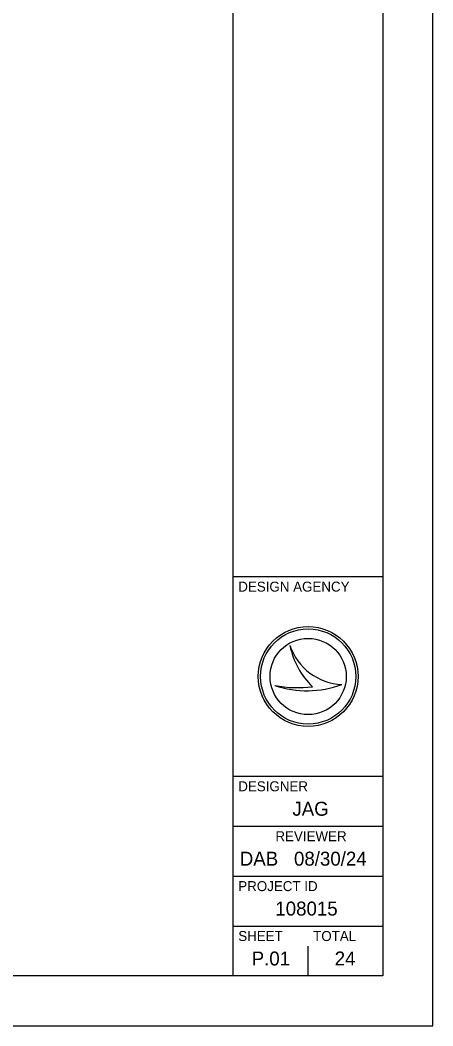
# Model space of a CAD drawing. Extents: x -10.1 to 68, y -9.5 to 29.2.
# Drawn here: x 29.86 to 34, y 0 to 10.07 of the extents above; entities that cross this region are included whole.
import ezdxf

# ---------------------------------------------------------------- set-up
doc = ezdxf.new("R2010")
doc.units = 0
for name, color, linetype in [('SH_Border', 7, 'Continuous'), ('SH_Cut_Line', 7, 'Continuous'), ('SH_Data', 7, 'Continuous')]:
    doc.layers.add(name, color=color, linetype=linetype)

msp = doc.modelspace()

# ---------------------------------------------------------------- linework, layer by layer
at = {"layer": 'SH_Border'}
for p, q in [((32, 0.5), (32, 21.5)), ((32, 4.5), (33.5, 4.5)), ((32, 2.5), (33.5, 2.5)), ((32, 2), (33.5, 2)), ((32, 1.5), (33.5, 1.5)), ((32, 1), (33.5, 1))]:
    msp.add_line(p, q, dxfattribs=at)
msp.add_lwpolyline([(1.5, 21.5), (33.5, 21.5), (33.5, 0.5), (1.5, 0.5)], close=True, dxfattribs=at)
at = {"layer": 'SH_Cut_Line'}
msp.add_lwpolyline([(0, 0), (34, 0), (34, 22), (0, 22)], close=True, dxfattribs=at)
at = {"layer": 'SH_Data'}
for p, q in [((32.567, 3.81), (32.567, 3.81)), ((32.75, 3.5), (32.75, 3.5)), ((32.417, 3.41), (32.417, 3.41)), ((33.087, 3.419), (33.087, 3.419)), ((32.75, 0.5), (32.75, 0.8)), ((32.375, 0.675), (32.375, 0.675))]:
    msp.add_line(p, q, dxfattribs=at)
for radius in [0.5, 0.477, 0.477, 0.382]:
    msp.add_circle((32.75, 3.5), radius, dxfattribs=at)
for centre, radius, start, end in [((33.116, 3.998), 0.58, 198.9257, 198.9319), ((33.347, 3.97), 0.796, 191.6379, 191.6421), ((33.116, 3.998), 0.58, 198.9319, 267.1657), ((33.347, 3.97), 0.796, 191.6421, 226.0947), ((32.739, 4.37), 1.013, 251.4576, 290.0832), ((32.648, 4.654), 1.266, 259.4964, 259.4995), ((32.739, 4.37), 1.013, 251.4527, 251.4576), ((32.648, 4.654), 1.266, 259.4995, 276.6672)]:
    msp.add_arc(centre, radius, start, end, dxfattribs=at)

# ---------------------------------------------------------------- texts
for s, height, p in [('DESIGN AGENCY', 0.1, (32.05, 4.35)), ('DESIGNER', 0.1, (32.05, 2.35)), ('JAG', 0.14, (32.592, 2.105)), ('REVIEWER', 0.1, (32.422, 1.85)), ('DAB', 0.14, (32.065, 1.605)), ('08/30/24', 0.14, (32.608, 1.605)), ('PROJECT ID', 0.1, (32.05, 1.35)), ('108015', 0.14, (32.421, 1.105)), ('SHEET', 0.1, (32.05, 0.85)), ('TOTAL', 0.1, (32.8, 0.85)), ('P.01', 0.14, (32.184, 0.605)), ('24', 0.14, (33.016, 0.605))]:
    msp.add_text(s, height=height, dxfattribs=at).set_placement(p)

doc.saveas('drawing.dxf')
